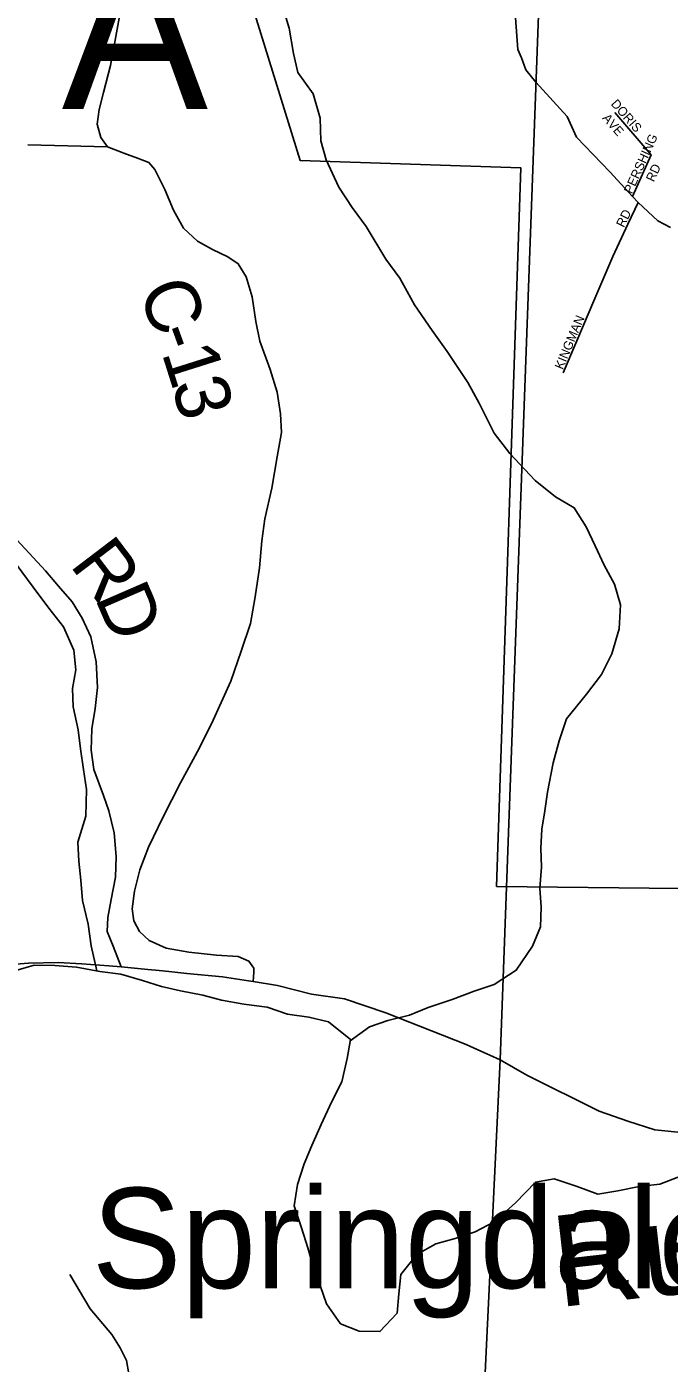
# Model space of a CAD drawing. Extents: x -84548 to 2262448, y -162180 to 525962.
# Drawn here: x 59468 to 62992, y 156808 to 164137 of the extents above; entities that cross this region are included whole.
import ezdxf

# ---------------------------------------------------------------- set-up
doc = ezdxf.new("R2010")
doc.units = 0
for name, color, linetype in [('GM_P_US_Location', 7, 'Continuous'), ('GM_X_Adjacent_County_Text', 7, 'Continuous'), ('GM_X_County_Road', 7, 'Continuous'), ('GM_X_Hydro', 7, 'Continuous'), ('GM_X_Major_Lake_Text', 7, 'Continuous'), ('GM_X_Minor_Lake', 7, 'Continuous'), ('GM_X_Minor_River_Text', 7, 'Continuous'), ('GM_X_State_Route', 7, 'Continuous'), ('GM_X_Township_Road', 7, 'Continuous'), ('GM_X_Township_ROW', 7, 'Continuous'), ('GM_X_Township_Subdivision_Text', 7, 'Continuous'), ('GM_X_Unincorporated_Text', 7, 'Continuous'), ('GM_X_US_Location', 7, 'Continuous'), ('GM_X_US_Route', 7, 'Continuous')]:
    doc.layers.add(name, color=color, linetype=linetype)

msp = doc.modelspace()

# ---------------------------------------------------------------- linework, layer by layer
at = {"layer": 'GM_X_Hydro'}
for p, q in [((62063.9, 158472), (62491.5, 170125.7)), ((61868.7, 154338.6), (62063.9, 158472))]:
    msp.add_line(p, q, dxfattribs=at)
at = {"layer": 'GM_X_Major_Lake_Text'}
for points in [[(62148.5, 164185.1), (62161.8, 164013), (62181.7, 163966.4), (62204.7, 163900.4), (62260.6, 163832.9), (62431.5, 163644.8), (62483.9, 163530.7), (62665.5, 163341.8), (62790.8, 163205.6), (62821, 163172.8), (62929.8, 163073.5), (62998.2, 163035.9)], [(59104.5, 158927.5), (59136.9, 158937.3), (59235.6, 158967.2), (59361.5, 158992.2), (59477.5, 159003.1), (59639.6, 159006.4), (59769.7, 158999.4), (59917.9, 158988.5), (59985.7, 158982), (60132.3, 158968.1), (60193.1, 158961.7)], [(60193.1, 158961.7), (60247.3, 158956.1), (60346.6, 158945.7), (60540.9, 158927.2), (60683.2, 158906.2), (60710.4, 158901.7), (60843.5, 158879.4), (61030, 158832.8), (61210.4, 158805.8), (61436.5, 158730.5), (61877.1, 158556.6), (61957.7, 158520)], [(61957.7, 158520), (62007.4, 158497.5)], [(62007.4, 158497.5), (62063.9, 158472), (62210.4, 158388.5), (62607.5, 158191.4), (62764, 158136.3), (62913.4, 158088.1), (63075.7, 158071.3), (63213.9, 158060.4), (63342, 158057.3), (63480, 158070.4), (63544.2, 158080.4), (63551.5, 158081.5)]]:
    msp.add_lwpolyline(points, dxfattribs=at)
at = {"layer": 'GM_X_Minor_Lake'}
msp.add_lwpolyline([(59985.7, 158982), (59942.5, 159094.9), (59908.7, 159176.3), (59913.1, 159252.5), (59931, 159351.1), (59954.3, 159473.8), (59957.8, 159588), (59947, 159716), (59918.4, 159837.6), (59888.6, 159921.1), (59835.4, 160064.2), (59821.1, 160170), (59824.6, 160286.3), (59842.2, 160398.9), (59855.7, 160513.3), (59848.6, 160655.4), (59819.7, 160791), (59771.4, 160894.1), (59717.4, 160983.1), (59641.5, 161069.7), (59569.7, 161154.3), (59413.9, 161323.2)], dxfattribs=at)
at = {"layer": 'GM_X_Minor_River_Text'}
for points in [[(60712.6, 158953.1), (60713.5, 158975.1), (60686.7, 159012.6), (60628.1, 159039.4), (60507.8, 159046.8), (60357.5, 159061.7), (60232.9, 159085), (60139.9, 159127.1), (60086.8, 159176.1), (60055.6, 159233.5), (60046.1, 159299.4), (60058, 159397.8), (60087.5, 159514.7), (60134.8, 159637.8), (60215.3, 159803.8), (60311.3, 159990.2), (60415.2, 160182.7), (60489.9, 160334.5), (60587.3, 160548.9), (60643.8, 160712.4), (60694.5, 160865.7), (60721.3, 161010.5), (60743.9, 161169.2), (60756.7, 161317.7), (60774.1, 161438.3), (60812.4, 161607.4), (60840.7, 161778.3), (60865.8, 161913), (60859.6, 162015), (60841, 162132.8), (60802.3, 162258.2), (60746.9, 162413.3), (60724.6, 162521), (60703.6, 162656.7), (60671.2, 162766.2), (60627.7, 162837.4), (60570.8, 162876.3), (60485.9, 162916.5), (60404.9, 162960.9), (60327.3, 163033.4), (60273.2, 163130.4), (60224.6, 163245.5), (60170.3, 163354.6), (60137.4, 163391.9), (60074.9, 163416.6), (60000.3, 163443.1), (59911.4, 163479.3), (59874.3, 163530.6), (59854.7, 163602.3), (59865, 163682.6), (59889, 163777.2), (59927.8, 163924.3), (59952.8, 164063.1), (59981.4, 164223.9)], [(60710.4, 158901.7), (60712.6, 158953.1)]]:
    msp.add_lwpolyline(points, dxfattribs=at)
at = {"layer": 'GM_X_State_Route'}
for points in [[(61241.7, 158576.3), (61347.1, 158652.6), (61449.1, 158688.7), (61567, 158716.8), (61669, 158758.9), (61801, 158803), (61921, 158849.2), (62031, 158885.3), (62153, 158963.5), (62241, 159095.9), (62284.9, 159202.2), (62288.9, 159308.6), (62282.9, 159412.9), (62290.9, 159529.2), (62286.9, 159633.5), (62292.9, 159737.8), (62308.9, 159838.1), (62324.9, 159940.4), (62354.9, 160100.9), (62388.9, 160221.3), (62428.9, 160341.6), (62538.8, 160478), (62620.8, 160584.4), (62676.8, 160698.7), (62716.8, 160835.1), (62724.8, 160967.5), (62690.8, 161079.8), (62634.8, 161184.1), (62584.8, 161290.5), (62536.8, 161394.8), (62470.8, 161499.1), (62368.8, 161559.2), (62256.8, 161649.5), (62116.8, 161797.9), (62030.8, 161908.3), (61948.8, 162072.7), (61886.8, 162187.1), (61772.8, 162355.6), (61690.8, 162471.9), (61594.8, 162612.3), (61514.8, 162758.8), (61436.8, 162863.1), (61328.8, 163041.6), (61252.9, 163145.9), (61178.9, 163258.2), (61110.9, 163406.7), (61080.9, 163511), (61076.9, 163635.3), (61038.9, 163769.7), (60954.9, 163886.1), (60930.9, 163990.4), (60906.9, 164128.8), (60870.9, 164249.1)], [(59851.5, 158960.4), (59821.2, 159097.8), (59805.2, 159216.1), (59773.2, 159346.5), (59765.2, 159456.8), (59753.2, 159561.2), (59747.2, 159665.5), (59791.1, 159807.9), (59795.1, 159954.3), (59779.1, 160064.7), (59763.1, 160177), (59749.1, 160281.3), (59723.1, 160407.7), (59719.1, 160508), (59737.1, 160610.3), (59725.1, 160718.6), (59669.1, 160847), (59589.1, 160949.3), (59503.1, 161063.6), (59409.1, 161190)], [(63059, 157836.2), (62941, 157790.1), (62827, 157778.1), (62709, 157754), (62601, 157735.9), (62487, 157778), (62361, 157820.2), (62259, 157802.1), (62149.1, 157687.8), (62031.1, 157583.4), (61927.1, 157529.3), (61817.1, 157493.1), (61711.1, 157463.1), (61607.1, 157404.9), (61519.2, 157294.5), (61509.2, 157188.2), (61499.2, 157083.9), (61405.2, 156981.6), (61291.2, 156983.6), (61189.2, 157023.7), (61111.2, 157134), (61077.2, 157234.3), (61039.2, 157338.6), (61009.2, 157440.9), (60975.2, 157551.3), (60935.2, 157671.6), (60953.2, 157788), (60989.2, 157902.3), (61031.2, 158002.6), (61083.1, 158117), (61139.1, 158239.3), (61195.1, 158351.7), (61225.1, 158480), (61243.1, 158584.4), (61123.1, 158680.6), (61015.1, 158706.7), (60897.1, 158722.7), (60787.1, 158760.8), (60659.1, 158776.9), (60535.1, 158798.9), (60433.2, 158827), (60311.2, 158851.1), (60207.2, 158875.1), (60103.2, 158907.2), (59983.2, 158941.3), (59869.2, 158957.4), (59741.2, 158979.4), (59621.2, 158989.5), (59509.2, 158991.4), (59407.2, 158961.3)]]:
    msp.add_lwpolyline(points, dxfattribs=at)
at = {"layer": 'GM_X_Township_ROW'}
for points in [[(59911.4, 163479.3), (59473.7, 163489.8)], [(59912.5, 156120.9), (59958.9, 156337.6), (60011.5, 156540.3), (60030.6, 156666.6), (60028, 156750.8), (60015.4, 156822.8), (59980.9, 156892.7), (59934.3, 156966.6), (59815.3, 157106), (59703.9, 157295.7)]]:
    msp.add_lwpolyline(points, dxfattribs=at)
at = {"layer": 'GM_X_Township_Subdivision_Text'}
msp.add_lwpolyline([(60536.3, 164797.8), (60966.7, 163404.3), (62177.5, 163363.6), (62044.8, 159423.4), (65563.8, 159384)], dxfattribs=at)
at = {"layer": 'GM_X_US_Location'}
for points in [[(62892, 163434.3), (62693.7, 163666.3)], [(62790.8, 163205.6), (62892, 163434.3)], [(62409.9, 162239.2), (62484.1, 162414.3), (62583.8, 162647.7), (62681.6, 162877.1), (62763.8, 163054.3), (62821, 163172.8)]]:
    msp.add_lwpolyline(points, dxfattribs=at)

# ---------------------------------------------------------------- texts
at = {"layer": 'GM_P_US_Location'}
msp.add_text('MARIETTA', height=900, rotation=0.00001, dxfattribs=at).set_placement((54377.7, 163685.6))
at = {"layer": 'GM_X_Adjacent_County_Text'}
msp.add_text('Springdale', height=550, rotation=0.00001, dxfattribs=at).set_placement((59825.3, 157220))
at = {"layer": 'GM_X_County_Road'}
for s, rotation, p in [('C', 291.64994, (60075.3, 162689.6)), ('-', 290.05447, (60165.4, 162462.6)), ('1', 287.5611, (60206.5, 162350.2)), ('3', 284.93746, (60261.3, 162177.5))]:
    msp.add_text(s, height=300, rotation=rotation, dxfattribs=at).set_placement(p)
at = {"layer": 'GM_X_Township_Road'}
for s, rotation, p in [('R', 307.27113, (59699.1, 161185.8)), ('D', 293.48128, (59838.7, 161006.2))]:
    msp.add_text(s, height=300, rotation=rotation, dxfattribs=at).set_placement(p)
at = {"layer": 'GM_X_Unincorporated_Text'}
msp.add_text('Run', height=499.99, rotation=6.47494, dxfattribs=at).set_placement((62383.5, 157114.8))
at = {"layer": 'GM_X_US_Route'}
for s, rotation, p in [('DORIS', 311.19004, (62668.8, 163712.2)), ('AVE', 310.81496, (62621.9, 163634.4)), ('PERSHING', 65.69563, (62786.2, 163217.3)), ('RD', 64.80073, (62906.7, 163282.6)), ('RD', 63.42523, (62742.4, 163032.8)), ('KINGMAN', 67.24834, (62407.7, 162253.5))]:
    msp.add_text(s, height=50, rotation=rotation, dxfattribs=at).set_placement(p)

doc.saveas('drawing.dxf')
